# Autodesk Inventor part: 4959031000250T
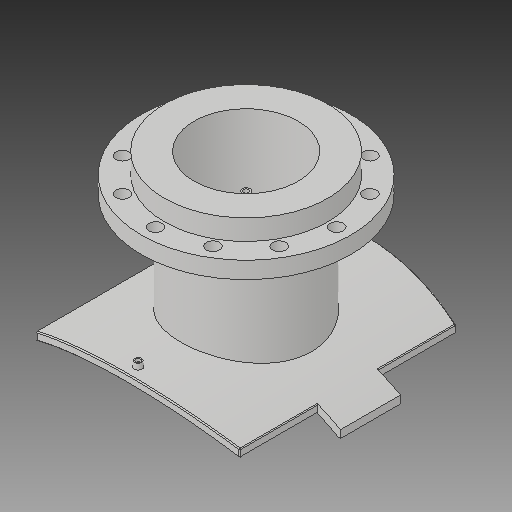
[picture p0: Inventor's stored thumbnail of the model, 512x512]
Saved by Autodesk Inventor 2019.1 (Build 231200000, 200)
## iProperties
Created: 2017-10
Part Number: 4959031000250T
Material: Generic
Description: PLASSON FLANGED BRANCH SADDLE 1000X250
Document SubType Name: Modeling
Designer: KIM
Mass: 2339.99 g
Surface Area: 3251.55 cm^2
Volume: 2339.99 cm^3
Density: 1 g/cm^3
Appearance: Default
Author: KIM
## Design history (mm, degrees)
derived "495904_495903.ipt"
feature "Solid1::495904_495903.ipt"
feature "Solid2::495904_495903.ipt"
tag "TaggingFeature1"
body "Solid1"
other parameters: "d1" = 15, "d2" = 398.7, "d4" = 0, "d6" = 117.5, "d7" = 0, "d12" = 525.6, "d13" = 14, "d14" = 211.5, "d16" = 5 deg, "d18" = 4, "d19" = 14, "d20" = 0, "d21" = 3, "d22" = 0, "d36" = 211.5, "d38" = 0, "d39" = 2, "d41" = 204, "d46" = 256, "d47" = 16, "d48" = 10.4, "d49" = 192.5, "d53" = 0, "d54" = 26, "d55" = 177.5, "d57" = 0, "d59" = 360 deg, "d61" = 33, "d63" = 0, "d66" = 275, "d67" = 15, "d68" = 137.5, "d70" = 0, "d71" = 2, "d72" = 443, "B_" = 443, "H_" = 275, "x_" = 15, "D_" = 16, "DN_" = 204, "t_" = 33, "s_" = 26, "Dp_" = 355
